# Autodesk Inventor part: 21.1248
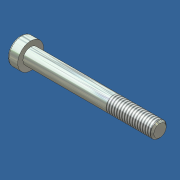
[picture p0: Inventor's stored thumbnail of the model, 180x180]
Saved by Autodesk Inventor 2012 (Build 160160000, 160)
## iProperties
Created: 2006-02
Part Number: 21.1248
Material: Steel, Mild
Description: M6X55 SHCS
Document SubType Name: Modeling
Standard: DIN 7984
Designer: Andy Moles
Standards Organization: DIN
Language: en-US
Size Designation: M6 x 40
Categories: <MemberInstance><Categories><Category DisplayName="Fasteners" InternalName="e4da775c-781d-43d5-af7c-5136215cf5a6" Mnemonic="FSTN"><Category DisplayName="Bolts"
Density: 7.86 g/cm^3
Vendor: S
Author: Andy Moles
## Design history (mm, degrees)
body "Solid1"
workplane "Work Plane1"
revolve "Body" stored, may be unused: angle "d10" = 90 deg
sketch "Sketch2"
  geometry: L1 (0, -6)-(0, 8) reference; L2 (-6, 0)-(8, 0) reference; L3 (2.309, 0)-(1.155, -2); L4 (1.155, -2)-(-1.155, -2); L5 (-1.155, -2)-(-2.309, 0); L6 (-2.309, 0)-(-1.155, 2); L7 (-1.155, 2)-(1.155, 2); L8 (1.155, 2)-(2.309, 0); 2 further points
  constraints: 12 end point, 1 coincident, 1 horizontal alignment, 1 point on line, 12 other
extrude "Slot" join sketch "Sketch2" stored distance "d11" = 10; taper "d12" = 0 deg
fillet "Fillet1" dims "d17" = 0.6 (= RR)
feature "Thread" dims "d13" = 18 (= GEL), "d14" = 0
chamfer "Chamfer1" distance "d15" = 0.61345 (= -0.5 x SPD + 0.5 x GD); stored, may be unused: second distance "d16" = 0.61345 (= GUL), angle "d27" = 45 deg
sketch "Sketch1"
  geometry: L1 (0.333, 0)-(55, 0); L2 (55, 0)-(55, 3); L3 (55, 3)-(37, 3); L4 (37, 3)-(36.386, 3); L5 (36.386, 3)-(0, 3); L6 (0, 3)-(0, 5); L7 (0, 5)-(-4, 5); L8 (-4, 5)-(-4, 2.309); L9 (-4, 2.309)-(-1, 2.309); L10 (-1, 2.309)-(0.333, 0); L11 (-9.4, 0)-(66.2, 0) reference; L12 (0, -0.5)-(0, 6.5) reference; L13 (37, 3)-(0, 3)
  constraints: 22 end point, 6 parallel, 2 collinear, 2 perpendicular, 1 horizontal, 1 midpoint
  dimensions: "d1" = 18 distance from line of L3.end L2 (= GEL); "d2" = 0.61355 distance of L4.end L3.end (computed from GAL); "d3" = 4 distance between parallel lines of L8 L6 (= KOH); "d4" = 3 distance of L8.end L9.end (= INTI); "d5" = 60 deg angle of L10 L1; "d6" = 6 diameter of L3 L1 (= GD); "d7" = 6 diameter of L5 L1 (= BDM); "d8" = 4.6188 diameter of L9 L1 (= 1.1547 x SW); "d9" = 10 diameter of L7 L1 (= KOD); "d26" = 55 distance between parallel lines of L12 L2 (= NLG)
other parameters: "GD" = 6 (= NND) [user parameter; used in 2 equation terms], "NLG" = 55 [user parameter; used in 1 equation term], "GEL" = 18 [user parameter; used in 2 equation terms], "KOD" = 10 [user parameter; used in 1 equation term], "KOH" = 4 [user parameter; used in 1 equation term], "INTI" = 3 [user parameter; used in 1 equation term], "GAL" = 0.61345 (= 0.61345 x PTC) [user parameter; used in 1 equation term], "GUL" = 0.61345 (= 0.61345 x PTC) [user parameter; used in 1 equation term], "BDM" = 6 (= NND) [user parameter; used in 1 equation term], "SW" = 4 [user parameter; used in 2 equation terms], "RR" = 0.6 [user parameter; used in 1 equation term], "SPD" = 4.7731 (= NND - 1.2269 x PTC) [user parameter; used in 1 equation term], "d19" = 0, "d28" = 0, "d29" = 0, "TOA" = 30 deg [user parameter], "GD1" = 4.7731 (= THREADDIA - 1.2269 x PTC) [user parameter], "THREADDIA" = 6 [user parameter; used in 1 equation term], "FAWI" = 45 deg [user parameter], "ANG" = 120 deg [user parameter], "PTC" = 1 [user parameter; used in 5 equation terms], "NND" = 6 [user parameter; used in 3 equation terms], "E0" = 4.62 (= 1.155 x SW) [user parameter]
